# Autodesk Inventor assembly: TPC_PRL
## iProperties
Shininess: 64.0
Length Units: 11272
Angle Units: 11279
Time Units: 11290
Mass Units: 11286
Length Display Precision: 3
Angle Display Precision: 2
Compacted: True
Part Number: TPC_PRL
Document SubType Name: Assembly
Created: 2004-08
Designer: Lori
Manufacturer: Standard
Standards Organization: Custom
Density: 0.0
Volumn: 0.0
Area: 0.0
PropertySet Name: Model Information
Control State: 0
Master: False
Checked Out: False
Author: Lori
